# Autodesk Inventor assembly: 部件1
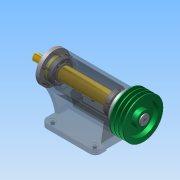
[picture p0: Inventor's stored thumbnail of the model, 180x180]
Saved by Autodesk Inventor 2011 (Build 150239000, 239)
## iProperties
Created: 2014-03
Part Number: 部件1
Document SubType Name: Assembly
Designer: Administrator
Author: Administrator
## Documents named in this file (13)
- C:\Documents and Settings\Administrator\桌面\机械制图\装配图\部件1.iam
- C:\Documents and Settings\Administrator\桌面\机械制图\装配图\6-6座体.ipt
- C:\Documents and Settings\Administrator\桌面\机械制图\装配图\6-6滚动轴承 30307 GB_T 297-94.ipt
- C:\Documents and Settings\Administrator\桌面\机械制图\装配图\p78  2.ipt
- C:\Documents and Settings\Administrator\桌面\机械制图\装配图\p792.ipt
- C:\Documents and Settings\Administrator\桌面\机械制图\装配图\6-6螺钉 GB_T 70.1 M8 x 16.ipt
- C:\Documents and Settings\Administrator\桌面\机械制图\装配图\6-6键GB_T 1096 - A 8 x 7 x 40.ipt
- C:\Documents and Settings\Administrator\桌面\机械制图\装配图\p77.ipt
- E:\寒假作业\6-6螺钉 GB_T 70.1 M8 x 16 - 副本.ipt
- C:\Documents and Settings\Administrator\桌面\机械制图\装配图\6-6带轮.ipt
- C:\Documents and Settings\Administrator\桌面\机械制图\装配图\6-6销GB_T 119.1-2000 Type B 3 h8 x 12.ipt
- C:\Documents and Settings\Administrator\桌面\机械制图\装配图\p78  1.ipt
- C:\Documents and Settings\Administrator\桌面\机械制图\装配图\6-6螺钉 GB_T 68 M6 x18.ipt
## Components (26 placed, 12 different names)
1. 6-6座体:1 — 插入:4, 插入:18
2. 6-6滚动轴承 30307 GB_T 297-94:1 — 配合:6, 配合:10
3. 6-6滚动轴承 30307 GB_T 297-94:2 — 配合:5, 配合:9
4. p78  2:1 — 配合:3, 配合:4, 配合:9
5. p792:2 — 插入:4, 配合:2, 插入:6, 插入:7, 插入:8, 插入:9, 插入:10, 配合:3, 配合:4, 配合:8
6. 6-6螺钉 GB_T 70.1 M8 x 16:1 — 插入:9
7. 6-6螺钉 GB_T 70.1 M8 x 16:2 — 插入:7
8. 6-6螺钉 GB_T 70.1 M8 x 16:3 — 插入:6
9. 6-6螺钉 GB_T 70.1 M8 x 16:4 — 配合:2
10. 6-6螺钉 GB_T 70.1 M8 x 16:5 — 插入:10
11. 6-6螺钉 GB_T 70.1 M8 x 16:6 — 插入:8
12. 6-6键GB_T 1096 - A 8 x 7 x 40:1 — 配合:11, 相切:1, 配合:12, 配合:14
13. p77:1 — 配合:5, 配合:6, 配合:7, 配合:8, 配合:10, 配合:11, 相切:1, 配合:12, 配合:13, 配合:15, 配合:16, 表面齐平:1, 配合:17, 配合:18, 插入:25
14. p792:3 — 插入:18, 插入:19, 插入:20, 插入:21, 插入:22, 插入:23, 插入:24, 配合:7
15. 6-6螺钉 GB_T 70.1 M8 x 16:7 — 插入:24
16. 6-6螺钉 GB_T 70.1 M8 x 16:8 — 插入:23
17. 6-6螺钉 GB_T 70.1 M8 x 16:9 — 插入:21
18. 6-6螺钉 GB_T 70.1 M8 x 16:10 — 插入:20
19. 6-6螺钉 GB_T 70.1 M8 x 16:11 — 插入:19
20. 6-6螺钉 GB_T 70.1 M8 x 16:12 — 插入:22
21. 6-6螺钉 GB_T 70.1 M8 x 16 - 副本:1 — 配合:17, 配合:18
22. 6-6带轮:1 — 配合:13, 配合:14, 配合:15
23. 6-6销GB_T 119.1-2000 Type B 3 h8 x 12:1 — 配合:16, 表面齐平:1, 插入:26
24. p78  1:1 — 插入:25, 插入:26, 配合:19, 相切:2, 插入:27
25. 6-6螺钉 GB_T 68 M6 x18:1 — 配合:19, 相切:2
26. 6-6销GB_T 119.1-2000 Type B 3 h8 x 12:2 — 插入:27
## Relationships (37: Mate 18, Insert 16, Tangent 2, Flush 1)
- 插入:4 [Insert]: 6-6座体:1 ↔ p792:2
- 配合:2 [Mate]: p792:2 ↔ 6-6螺钉 GB_T 70.1 M8 x 16:4
- 插入:6 [Insert]: p792:2 ↔ 6-6螺钉 GB_T 70.1 M8 x 16:3
- 插入:7 [Insert]: p792:2 ↔ 6-6螺钉 GB_T 70.1 M8 x 16:2
- 插入:8 [Insert]: p792:2 ↔ 6-6螺钉 GB_T 70.1 M8 x 16:6
- 插入:9 [Insert]: p792:2 ↔ 6-6螺钉 GB_T 70.1 M8 x 16:1
- 插入:10 [Insert]: p792:2 ↔ 6-6螺钉 GB_T 70.1 M8 x 16:5
- 插入:18 [Insert]: 6-6座体:1 ↔ p792:3
- 插入:19 [Insert]: p792:3 ↔ 6-6螺钉 GB_T 70.1 M8 x 16:11
- 插入:20 [Insert]: p792:3 ↔ 6-6螺钉 GB_T 70.1 M8 x 16:10
- 插入:21 [Insert]: p792:3 ↔ 6-6螺钉 GB_T 70.1 M8 x 16:9
- 插入:22 [Insert]: p792:3 ↔ 6-6螺钉 GB_T 70.1 M8 x 16:12
- 插入:23 [Insert]: p792:3 ↔ 6-6螺钉 GB_T 70.1 M8 x 16:8
- 插入:24 [Insert]: p792:3 ↔ 6-6螺钉 GB_T 70.1 M8 x 16:7
- 配合:3 [Mate]: p78  2:1 ↔ p792:2
- 配合:4 [Mate]: p78  2:1 ↔ p792:2
- 配合:5 [Mate]: 6-6滚动轴承 30307 GB_T 297-94:2 ↔ p77:1
- 配合:6 [Mate]: 6-6滚动轴承 30307 GB_T 297-94:1 ↔ p77:1
- 配合:7 [Mate]: p77:1 ↔ p792:3
- 配合:8 [Mate]: p792:2 ↔ p77:1
- 配合:9 [Mate]: 6-6滚动轴承 30307 GB_T 297-94:2 ↔ p78  2:1
- 配合:10 [Mate]: 6-6滚动轴承 30307 GB_T 297-94:1 ↔ p77:1
- 配合:11 [Mate]: 6-6键GB_T 1096 - A 8 x 7 x 40:1 ↔ p77:1
- 相切:1 [Tangent]: 6-6键GB_T 1096 - A 8 x 7 x 40:1 ↔ p77:1
- 配合:12 [Mate]: 6-6键GB_T 1096 - A 8 x 7 x 40:1 ↔ p77:1
- 配合:13 [Mate]: p77:1 ↔ 6-6带轮:1
- 配合:14 [Mate]: 6-6键GB_T 1096 - A 8 x 7 x 40:1 ↔ 6-6带轮:1
- 配合:15 [Mate]: p77:1 ↔ 6-6带轮:1
- 配合:16 [Mate]: p77:1 ↔ 6-6销GB_T 119.1-2000 Type B 3 h8 x 12:1
- 表面齐平:1 [Flush]: p77:1 ↔ 6-6销GB_T 119.1-2000 Type B 3 h8 x 12:1
- 配合:17 [Mate]: p77:1 ↔ 6-6螺钉 GB_T 70.1 M8 x 16 - 副本:1
- 配合:18 [Mate]: p77:1 ↔ 6-6螺钉 GB_T 70.1 M8 x 16 - 副本:1
- 插入:25 [Insert]: p77:1 ↔ p78  1:1
- 插入:26 [Insert]: 6-6销GB_T 119.1-2000 Type B 3 h8 x 12:1 ↔ p78  1:1
- 配合:19 [Mate]: p78  1:1 ↔ 6-6螺钉 GB_T 68 M6 x18:1
- 相切:2 [Tangent]: p78  1:1 ↔ 6-6螺钉 GB_T 68 M6 x18:1
- 插入:27 [Insert]: p78  1:1 ↔ 6-6销GB_T 119.1-2000 Type B 3 h8 x 12:2
